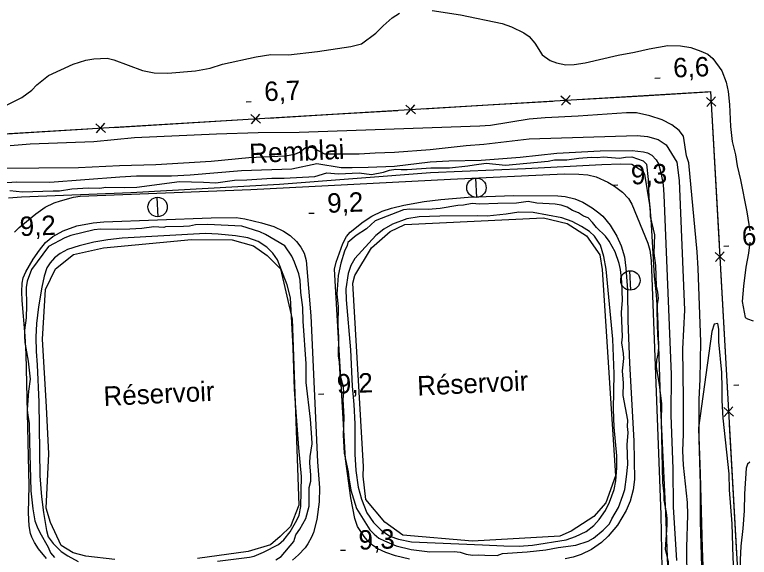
# Model space of a CAD drawing. Extents: x 336540 to 340074, y 5572036 to 5573747.
# Drawn here: x 337475.9 to 337589.4, y 5572956.1 to 5573040 of the extents above; entities that cross this region are included whole.
import ezdxf

# ---------------------------------------------------------------- set-up
doc = ezdxf.new("R2010")
doc.units = 0
for name, color, linetype in [('Niveau 19', 7, 'Continuous'), ('Niveau 2', 7, 'Continuous'), ('Niveau 27', 7, 'Continuous'), ('Niveau 3', 7, 'Continuous'), ('Niveau 33', 7, 'Continuous'), ('Niveau 36', 7, 'Continuous'), ('Niveau 37', 7, 'Continuous')]:
    doc.layers.add(name, color=color, linetype=linetype)

msp = doc.modelspace()

# ---------------------------------------------------------------- linework, layer by layer
at = {"layer": 'Niveau 19'}
for points in [[(337475.82, 5573006.41), (337476.57, 5573007.11), (337479.15, 5573009.22), (337480.58, 5573010.26), (337481.94, 5573010.91), (337482.94, 5573011.25), (337484.96, 5573011.78), (337485.99, 5573011.93), (337512.36, 5573012.99), (337543.2, 5573014.59), (337560.77, 5573015.4), (337563.06, 5573015.37), (337564.43, 5573015.27), (337565.73, 5573014.95), (337567.53, 5573014.12), (337568.56, 5573013.5), (337569.78, 5573012.56), (337570.74, 5573011.57), (337571.26, 5573010.73), (337573.73, 5573004.71)], [(337527.01, 5572971.35), (337525.26, 5573000.67), (337525.55, 5573001.75), (337526.59, 5573004.66), (337527.16, 5573005.7), (337527.72, 5573006.37), (337529.7, 5573007.97), (337531.03, 5573008.85), (337532.64, 5573009.61), (337534.08, 5573010.1), (337536, 5573010.58), (337539.13, 5573011.14), (337541.7, 5573011.45), (337545.93, 5573011.81), (337552.97, 5573012.08), (337559.78, 5573012), (337560.94, 5573011.89), (337562.41, 5573011.54), (337563.64, 5573011.04), (337565.1, 5573010.17), (337566.13, 5573009.4), (337566.73, 5573008.84), (337567.88, 5573007.49), (337568.92, 5573005.78), (337569.57, 5573004.28), (337570.08, 5573002.59), (337570.33, 5573000.8), (337570.55, 5572997.49), (337570.64, 5572992.69), (337570.9, 5572986.15), (337571.53, 5572974.14), (337571.63, 5572968.17), (337571.42, 5572966.56), (337570.98, 5572964.79), (337570.38, 5572963.36), (337569.01, 5572961.07), (337567.58, 5572959.37), (337566.55, 5572958.41), (337564.99, 5572957.33), (337563.39, 5572956.57), (337562.16, 5572956.15), (337560.94, 5572955.9)], [(337480.8, 5572955.95), (337479.56, 5572957.44), (337478.93, 5572958.43), (337478.52, 5572959.25), (337478.33, 5572959.79), (337478.11, 5572961.01), (337478.02, 5572962.97), (337478.12, 5572967.18), (337477.63, 5572987.52), (337477.48, 5572990.38), (337477.02, 5572995.83), (337476.96, 5572997.17), (337477.01, 5572998.51), (337477.19, 5572999.32), (337477.58, 5573000.24), (337478.74, 5573002.23), (337479.68, 5573003.61), (337480.62, 5573004.77), (337481.74, 5573005.74), (337483.37, 5573006.59), (337485.49, 5573007.36), (337487.99, 5573007.82), (337489.63, 5573007.96), (337506.2, 5573008.62), (337510.08, 5573008.68), (337511.44, 5573008.47), (337514.02, 5573007.84), (337515.89, 5573007.26), (337517.42, 5573006.56), (337518.42, 5573005.85), (337519.42, 5573004.94), (337520.1, 5573004.09), (337520.6, 5573003.14), (337520.92, 5573002), (337521.61, 5572993.43), (337522.64, 5572970.87)], [(337573.73, 5573004.71), (337574.03, 5573003.62), (337574.24, 5573002.02), (337575.74, 5572962.68), (337575.87, 5572954.34), (337575.78, 5572953.58), (337575.21, 5572952.2), (337574.63, 5572951.26), (337573.73, 5572950.18), (337572.28, 5572948.79), (337571.01, 5572948), (337569.12, 5572947.08), (337566.32, 5572945.88), (337562.31, 5572944.34), (337561.12, 5572943.72), (337558.63, 5572941.81), (337557.03, 5572939.27)], [(337522.64, 5572970.87), (337522.96, 5572966.87), (337522.9, 5572964.72), (337522.57, 5572961.94), (337522.05, 5572959.97), (337521.75, 5572959.22), (337521.18, 5572958.18), (337520.73, 5572957.57), (337519.74, 5572956.49), (337518.77, 5572955.68)], [(337536.89, 5572955.82), (337534.72, 5572956.34), (337533.22, 5572956.86), (337531.97, 5572957.44), (337531.16, 5572957.99), (337530.31, 5572958.79), (337529.85, 5572959.34), (337528.85, 5572960.89), (337528.42, 5572962.13), (337527.81, 5572965.32), (337527.01, 5572971.35)]]:
    msp.add_lwpolyline(points, dxfattribs=at)
at = {"layer": 'Niveau 2'}
for points in [[(337473.22, 5573025.35), (337476.95, 5573027.23), (337478.5, 5573028.32), (337479.28, 5573029.16), (337481.11, 5573030.62), (337484.88, 5573032.35), (337486.88, 5573032.99), (337488.09, 5573033.16), (337490.13, 5573033.28), (337491.16, 5573033.04), (337495.61, 5573031.39), (337497.4, 5573031.02), (337499.52, 5573030.96), (337503.8, 5573031.34), (337506.08, 5573031.75), (337507.97, 5573032.35), (337513.16, 5573033.51), (337515.46, 5573033.83), (337518.18, 5573033.79), (337522.68, 5573034.31), (337527.8, 5573035.07), (337529.45, 5573035.49), (337531.69, 5573037.14), (337532.79, 5573038.31), (337534.18, 5573039.52), (337535.35, 5573040.27)], [(337540.36, 5573040.66), (337544.75, 5573039.98), (337551.18, 5573038.66), (337552.65, 5573038.12), (337554.56, 5573037.18), (337555.37, 5573036.62)], [(337555.37, 5573036.62), (337556.26, 5573035.63), (337557.37, 5573033.78), (337558.6, 5573032.93), (337559.58, 5573032.55), (337561.04, 5573032.24), (337562.33, 5573032.31), (337564.04, 5573032.58), (337569.1, 5573033.77), (337571.65, 5573034.22), (337573.9, 5573034.75), (337576.8, 5573035.24), (337578.77, 5573035.22), (337580.36, 5573034.93), (337581.92, 5573034.38), (337582.96, 5573033.91), (337583.76, 5573033.24), (337585.14, 5573031.31), (337585.82, 5573029.56), (337586.12, 5573028.14), (337586.33, 5573026.11), (337586.5, 5573022.72), (337586.75, 5573020.38), (337587.24, 5573018.34), (337587.5, 5573016.62), (337588.04, 5573014.49), (337589, 5573009.53), (337589.45, 5573006.59)], [(337506.25, 5573017.34), (337512.06, 5573017.91), (337517.64, 5573018.17), (337519.15, 5573018.47), (337519.86, 5573018.78), (337520.95, 5573019.6), (337521.86, 5573019.49), (337523.74, 5573018.52), (337529.09, 5573018.5), (337531.59, 5573018.67), (337534.54, 5573018.76), (337540.05, 5573019.17), (337545.65, 5573019.79), (337548.36, 5573019.99), (337555.37, 5573020.82), (337572.06, 5573021.34), (337573.64, 5573021.2), (337575.29, 5573020.72), (337576.53, 5573019.91), (337578.17, 5573017.23), (337578.54, 5573014.38), (337579.38, 5572994.32)], [(337473.82, 5573014.01), (337476.19, 5573014.17), (337481.3, 5573014.1), (337492.12, 5573014.95), (337494.67, 5573015.08), (337500.1, 5573015.11), (337502.99, 5573015.23), (337510.91, 5573015.9), (337518.67, 5573016.16), (337522.54, 5573017.02), (337526.33, 5573016.4), (337528.01, 5573016.36), (337530.49, 5573016.43), (337534.55, 5573016.6), (337540.07, 5573017.25), (337542.96, 5573017.44), (337547.97, 5573017.53), (337553.96, 5573017.97), (337559.67, 5573018.58), (337566.34, 5573018.98), (337571.27, 5573019.01), (337573.05, 5573018.81), (337573.64, 5573018.63), (337574.34, 5573018.27), (337575.01, 5573017.57), (337575.35, 5573016.96), (337575.71, 5573015.61), (337576.07, 5573013.69), (337576.19, 5573012.15), (337577.31, 5572984.38), (337577.24, 5572978.08), (337577.55, 5572969.79), (337577.61, 5572963.9), (337578.15, 5572955.62)], [(337473.43, 5573016.26), (337485.74, 5573016.39), (337492.07, 5573016.7), (337497.66, 5573016.87), (337506.25, 5573017.34)], [(337475.13, 5573012.81), (337477.05, 5573012.63), (337481.82, 5573012.8), (337482.78, 5573012.76), (337484.68, 5573013.09), (337487.26, 5573013.26), (337489.01, 5573013.19), (337489.96, 5573013.33), (337492.83, 5573013.28), (337494.74, 5573013.33), (337501.35, 5573014.22), (337505.06, 5573014.14), (337506.97, 5573014.01), (337509.83, 5573014.42), (337511.74, 5573014.47), (337515.61, 5573014.73), (337517.52, 5573014.72), (337522.23, 5573015), (337524.08, 5573015.55), (337525.88, 5573015.42), (337529.08, 5573015.55), (337530.99, 5573015.32), (337532.84, 5573015.64), (337533.79, 5573015.95), (337534.74, 5573016.14), (337535.58, 5573016.05), (337536.54, 5573016.07), (337540.19, 5573016.32), (337543.05, 5573016.34), (337545.91, 5573016.63), (337546.86, 5573016.82), (337548.71, 5573017.03), (337551.69, 5573016.77), (337558.31, 5573017.38), (337559.26, 5573017.57), (337561.17, 5573017.56), (337563.02, 5573017.83), (337564.93, 5573017.98), (337565.88, 5573017.95), (337566.84, 5573018.03), (337569.32, 5573017.81), (337570.27, 5573018), (337571.22, 5573018.02), (337572.98, 5573017.39), (337573.5, 5573016.89), (337573.78, 5573014.54), (337573.84, 5573011.67), (337574.06, 5573009.77), (337574.08, 5573008.81), (337574.76, 5573005.96), (337574.66, 5573003.15), (337574.87, 5573001.24), (337575.01, 5572998.04), (337575.2, 5572997.09), (337575.28, 5572996.14), (337575.13, 5572995.18), (337575.1, 5572994.22), (337575.19, 5572990.4), (337575.32, 5572989.45), (337575.34, 5572988.5), (337575.25, 5572987.54), (337575.05, 5572986.58), (337575.02, 5572985.62), (337575.48, 5572982.77), (337575.83, 5572979.91), (337575.78, 5572977.04), (337575.95, 5572967.66), (337576.16, 5572965.92), (337576.18, 5572964.96)], [(337568.16, 5572962.07), (337569.18, 5572963.84), (337569.87, 5572965.66), (337570.13, 5572966.62), (337570.42, 5572968.54), (337570.6, 5572970.45), (337570.53, 5572973.49), (337570.65, 5572975.4), (337570.57, 5572976.35), (337570.61, 5572977.31), (337569.9, 5572981.11), (337569.97, 5572983.03), (337569.81, 5572984.93), (337569.99, 5572986.85), (337569.97, 5572987.64), (337569.71, 5572989.26), (337569.8, 5572990.22), (337569.65, 5572993.98), (337569.78, 5572995.89), (337569.71, 5572998.7), (337569.5, 5573000.61), (337569.3, 5573001.56), (337568.64, 5573003.34), (337567.71, 5573005.01), (337567.18, 5573005.78), (337565.75, 5573007.1), (337565.17, 5573007.87), (337564.48, 5573008.58), (337563.79, 5573008.85), (337563, 5573009.39), (337562.09, 5573009.76), (337561.23, 5573010.25), (337560.33, 5573010.57), (337559.37, 5573010.71), (337556.55, 5573010.87), (337555.2, 5573011.12), (337553.41, 5573010.85), (337550.54, 5573010.84), (337547.68, 5573010.71), (337546.55, 5573010.8), (337545.21, 5573010.54), (337544.37, 5573010.52), (337541.63, 5573010.06), (337539.77, 5573009.91), (337536.91, 5573009.95), (337535.96, 5573009.82), (337531.56, 5573008.14), (337530.24, 5573006.92), (337528.63, 5573005.87), (337527.36, 5573004.78), (337527.26, 5573004.32), (337526.83, 5573003.47), (337526.26, 5573001.6), (337525.86, 5572999.68), (337525.64, 5572996.81), (337525.86, 5572994.9), (337525.81, 5572992.03), (337525.91, 5572990.13), (337525.87, 5572987.26), (337526, 5572986.31), (337526.1, 5572984.4), (337526.65, 5572982.5), (337526.68, 5572981.54), (337526.59, 5572980.59), (337526.71, 5572977.72), (337526.61, 5572975.08), (337526.79, 5572972.22), (337527.41, 5572969.36), (337527.49, 5572968.41), (337527.82, 5572966.51), (337528.67, 5572963.66), (337530.72, 5572960.39), (337531.41, 5572959.68), (337532.15, 5572959.08), (337533.01, 5572958.65), (337534.82, 5572957.91), (337537.14, 5572957.34), (337540.01, 5572956.96), (337543.78, 5572957), (337544.73, 5572956.91), (337545.64, 5572956.59), (337546.6, 5572956.45), (337547.55, 5572956.52), (337548.51, 5572956.43), (337550.42, 5572956.42), (337551.26, 5572956.72), (337555.07, 5572956.98), (337557.93, 5572957.28), (337559.83, 5572957.66), (337562.58, 5572958.01), (337564.47, 5572958.61), (337565.3, 5572959.08), (337566.79, 5572960.3), (337567.78, 5572961.28), (337568.16, 5572962.07)], [(337548.16, 5572958.06), (337551.46, 5572957.88), (337553.82, 5572957.86), (337555.89, 5572958), (337561.08, 5572958.81), (337562.53, 5572959.35), (337564.17, 5572960.12), (337565.34, 5572961.03), (337566.19, 5572961.99), (337567.17, 5572963.36), (337567.77, 5572964.63), (337568.49, 5572966.58), (337568.75, 5572967.94), (337568.93, 5572969.96), (337568.92, 5572971.83), (337568.5, 5572976.25), (337568.42, 5572979.04), (337568.5, 5572984.47), (337568.29, 5572989.87), (337567.25, 5573000.66), (337566.92, 5573002.6), (337566.38, 5573004.39), (337565.46, 5573005.78), (337564.69, 5573006.47), (337563.44, 5573007.28), (337561.99, 5573008.02), (337560.44, 5573008.6), (337555.99, 5573009.43), (337553.77, 5573009.48), (337551.83, 5573009.17), (337548.89, 5573008.85), (337547.33, 5573008.91), (337541.58, 5573008.87), (337538.37, 5573008.76), (337536.48, 5573008.45), (337534.24, 5573007.62), (337532.91, 5573006.84), (337531.68, 5573005.85), (337528.41, 5573002.32), (337527.8, 5573001.23), (337527.39, 5573000.01), (337527.06, 5572997.64), (337527.1, 5572995.9), (337527.75, 5572988.18), (337528.03, 5572982.57), (337528.29, 5572979.75), (337528.41, 5572976.78), (337528.42, 5572972.06), (337528.6, 5572969.55), (337528.96, 5572966.97), (337529.44, 5572965.12), (337530.29, 5572963.02), (337531.3, 5572961.49), (337532.48, 5572960.3), (337533.85, 5572959.37), (337535.19, 5572958.93), (337537.16, 5572958.53), (337548.16, 5572958.06)], [(337519.33, 5572959.62), (337519.93, 5572960.47), (337520.84, 5572962.12), (337521.36, 5572964.05), (337521.35, 5572966.91), (337521.61, 5572967.88), (337521.64, 5572968.83), (337521.48, 5572970.74), (337521.52, 5572971.7), (337521.81, 5572973.67), (337521.78, 5572974.63), (337521.6, 5572977.49), (337520.91, 5572983.15), (337520.9, 5572986.01), (337520.46, 5572992.64), (337520.41, 5572994.72), (337520.07, 5572997.07), (337519.97, 5572998.98), (337519.78, 5572999.93), (337519.12, 5573001.77), (337518.7, 5573002.66), (337517.6, 5573004.26), (337514.63, 5573006.05), (337513.73, 5573006.42), (337510.95, 5573007.31), (337505.66, 5573007.57), (337503.81, 5573007.53), (337502.86, 5573007.34), (337501.96, 5573007.26), (337499.15, 5573007.19), (337498.93, 5573007.13), (337497.35, 5573007.21), (337495.51, 5573006.94), (337493.65, 5573006.84), (337491.74, 5573006.79), (337489.1, 5573006.84), (337488.15, 5573006.76), (337484.52, 5573005.89), (337483.62, 5573005.53), (337481.07, 5573004.18), (337478.46, 5573000.63), (337477.77, 5572998.81), (337477.62, 5572997.85), (337477.69, 5572995.05), (337477.62, 5572993.13), (337477.39, 5572991.22), (337477.36, 5572990.26), (337477.43, 5572989.31), (337477.95, 5572986.45), (337478.24, 5572983.65), (337478.01, 5572981.79), (337477.79, 5572978.91), (337477.87, 5572978.02), (337478.12, 5572976.84), (337478.13, 5572973.98), (337478.37, 5572966.39), (337478.66, 5572963.59), (337478.99, 5572961.74), (337479.35, 5572960.85), (337479.76, 5572959.96), (337481.05, 5572957.69), (337481.41, 5572956.8), (337481.99, 5572956.08)], [(337507.22, 5572955.53), (337512.14, 5572956.16), (337512.88, 5572956.31), (337514.31, 5572956.89), (337516.64, 5572958.08), (337517.48, 5572958.8), (337518.43, 5572960.06), (337519.48, 5572961.85), (337519.84, 5572962.64), (337520.07, 5572964), (337520.21, 5572968.63), (337519.79, 5572973.03), (337519.11, 5572982.08), (337518.9, 5572988.49), (337518.47, 5572996.25), (337517.95, 5572998.23), (337516.47, 5573002.11), (337515.75, 5573003.14), (337514.83, 5573004.07), (337513.5, 5573004.96), (337511.91, 5573005.49), (337509.96, 5573005.81), (337507.29, 5573006.08), (337505.37, 5573006.16), (337492.48, 5573005.45), (337490.28, 5573005.2), (337488.08, 5573004.82), (337485.82, 5573004.28), (337484.02, 5573003.69), (337482.87, 5573003.1), (337482, 5573002.43), (337481.32, 5573001.67), (337480.84, 5573000.85), (337480.43, 5572999.56), (337480.08, 5572997.88), (337479.55, 5572994.83), (337479.24, 5572992.29), (337479.14, 5572990.16), (337479.17, 5572987.95), (337479.36, 5572985.86), (337479.6, 5572980.11), (337479.74, 5572968.72), (337479.99, 5572965.49), (337480.3, 5572963.04), (337480.77, 5572960.26), (337481.06, 5572959.28), (337481.82, 5572958.24), (337483.06, 5572957.01), (337484.06, 5572956.34), (337485.67, 5572955.48)], [(337589.47, 5573004.85), (337589.28, 5573003.15), (337588.87, 5573000.99), (337588.47, 5572998.02), (337588.31, 5572995.69), (337588.73, 5572993.19), (337589.1, 5572992.97), (337589.99, 5572992.69)], [(337579.38, 5572994.32), (337579.07, 5572988.36), (337579.18, 5572980.61), (337579.17, 5572975.17), (337579.08, 5572972.6), (337579.17, 5572970.36), (337579.79, 5572964.57), (337579.84, 5572962.67), (337579.69, 5572957.63), (337579.74, 5572952.43)], [(337586.29, 5572969.05), (337585.36, 5572977.64), (337585.19, 5572980.37), (337585.22, 5572982.25), (337585.13, 5572984.67), (337584.69, 5572989.42), (337584.67, 5572991.39), (337584.54, 5572992.29), (337583.94, 5572992.17), (337583.58, 5572991.01), (337581.52, 5572976.14), (337581.81, 5572967.37), (337581.79, 5572961.65), (337582.15, 5572949.44)], [(337589.48, 5572970.82), (337589.11, 5572970.51), (337588.92, 5572969.88), (337588.67, 5572965.93), (337588.59, 5572963.28), (337588.38, 5572960.59), (337588.06, 5572957.82), (337587.97, 5572955.72), (337588.15, 5572950.67), (337588.04, 5572948.54), (337588.08, 5572946.27), (337588.45, 5572940.88), (337588.44, 5572938.94), (337588.29, 5572936.69), (337587.9, 5572936.72), (337587.57, 5572937.33), (337587.33, 5572941.04), (337587.4, 5572943.09), (337587.07, 5572953.07), (337586.87, 5572956.1), (337586.76, 5572961.31), (337586.34, 5572966.57), (337586.29, 5572969.05)], [(337576.18, 5572964.96), (337576.56, 5572963.06), (337576.64, 5572962.11), (337576.66, 5572961.15), (337576.41, 5572957.33), (337576.85, 5572955.48), (337576.87, 5572954.53), (337576.58, 5572952.61), (337576.68, 5572950.93), (337576.21, 5572949.34), (337575.52, 5572947.53), (337574.95, 5572945.66), (337574.49, 5572943.79), (337574.1, 5572943.45), (337573.27, 5572942.92), (337571.2, 5572942.65), (337568.35, 5572941.79), (337567.4, 5572941.77), (337566.45, 5572941.52), (337564.82, 5572941.48), (337560.11, 5572941.14), (337558.23, 5572941.21)], [(337516.22, 5572955.72), (337517.05, 5572956.24), (337519.02, 5572958.54), (337519.33, 5572959.62)]]:
    msp.add_lwpolyline(points, dxfattribs=at)
at = {"layer": 'Niveau 27'}
for points in [[(337582.59, 5572946.44), (337582.16, 5572957.53), (337581.86, 5572968.97), (337581.62, 5572974.82), (337581.65, 5572980.54), (337581.79, 5572983.64), (337581.9, 5572989.45), (337581.49, 5573000.77), (337581.34, 5573003.34), (337580.02, 5573017.09), (337579.7, 5573018.18), (337579.22, 5573021.21), (337578.55, 5573022.11), (337577.42, 5573022.98), (337575.91, 5573023.75), (337574.03, 5573024.38), (337571.94, 5573024.85), (337570.39, 5573024.85), (337562.94, 5573024.3), (337557.86, 5573024.07), (337555.37, 5573023.84), (337549.41, 5573022.86), (337547.72, 5573022.77), (337519.84, 5573021.79), (337513.5, 5573021.72), (337507.05, 5573021.54), (337494.39, 5573020.95), (337488.09, 5573020.37), (337478.23, 5573019.98), (337475.17, 5573019.74)], [(337474.92, 5573011.72), (337476.89, 5573011.86), (337493.79, 5573012.52), (337516.76, 5573013.82), (337540.13, 5573015.63), (337554.78, 5573016.22), (337566.62, 5573016.84), (337569.53, 5573016.95), (337571.21, 5573016.9), (337572.92, 5573015.82), (337573.17, 5573015.33), (337573.98, 5573010.59), (337574.18, 5573008.4), (337574.68, 5572999.56), (337574.99, 5572996.72), (337575.21, 5572993.54), (337575.64, 5572979.19), (337576.43, 5572963.02), (337577.18, 5572943.76)]]:
    msp.add_lwpolyline(points, dxfattribs=at)
at = {"layer": 'Niveau 3'}
for p, q in [((337574.81, 5573030.21), (337575.61, 5573030.25)), ((337511.61, 5573026.56), (337512.4, 5573026.59)), ((337568.29, 5573013.67), (337569.09, 5573013.71)), ((337521.34, 5573009.3), (337522.14, 5573009.32)), ((337585.43, 5573004.21), (337586.23, 5573004.25)), ((337586.98, 5572982.74), (337587.78, 5572982.78)), ((337522.83, 5572981.34), (337523.63, 5572981.38)), ((337526.19, 5572957.2), (337526.99, 5572957.24))]:
    msp.add_line(p, q, dxfattribs=at)
at = {"layer": 'Niveau 33'}
for points in [[(337529.79, 5572970.15), (337528.14, 5572998.48), (337528.44, 5572999.7), (337531.01, 5573003.94), (337533.9, 5573006.5), (337536.14, 5573007.58), (337557.58, 5573008.62), (337561.25, 5573007.71), (337564.24, 5573005.8), (337566.31, 5573002.87), (337566.66, 5573000.59), (337568.69, 5572968.74), (337567.2, 5572964.55), (337565.38, 5572962.41), (337561.86, 5572960.18), (337560.09, 5572959.37), (337546.61, 5572958.59), (337535.82, 5572959.52), (337533.07, 5572961.56), (337530.12, 5572965.05), (337529.7, 5572968.66), (337529.79, 5572970.15)], [(337480.74, 5572963.72), (337481.13, 5572972.11), (337480.78, 5572979.36), (337480.15, 5572989.86), (337480.62, 5572997.5), (337482.16, 5573000.72), (337484.95, 5573002.92), (337489.6, 5573003.99), (337503.18, 5573005.25), (337509.46, 5573005.19), (337512.77, 5573004.27), (337514.89, 5573002.8), (337516.92, 5573000.72), (337518.75, 5572992.94), (337519.78, 5572964.19), (337518.49, 5572960.86), (337516.88, 5572959.33), (337515.37, 5572958.04), (337511.92, 5572957.03), (337504.13, 5572955.92)], [(337491.34, 5572955.79), (337486.85, 5572956.3), (337484.89, 5572956.81), (337483.03, 5572957.93), (337481.41, 5572961.48), (337480.74, 5572963.72)]]:
    msp.add_lwpolyline(points, dxfattribs=at)
at = {"layer": 'Niveau 36'}
for p, q in [((337547.3, 5573011.75), (337547.15, 5573014.74)), ((337498.03, 5573008.77), (337497.88, 5573011.76)), ((337571.09, 5572997.42), (337570.94, 5573000.41))]:
    msp.add_line(p, q, dxfattribs=at)
for centre in [(337547.22, 5573013.26), (337497.95, 5573010.28), (337571.01, 5572998.93)]:
    msp.add_circle(centre, 1.5, dxfattribs=at)
at = {"layer": 'Niveau 37'}
for p, q in [((337561.76, 5573026.11), (337560.27, 5573027.43)), ((337560.35, 5573026.02), (337561.68, 5573027.52)), ((337582.83, 5573025.8), (337584.16, 5573027.29)), ((337582.75, 5573027.21), (337584.24, 5573025.88)), ((337537.81, 5573024.67), (337536.31, 5573026)), ((337536.39, 5573024.59), (337537.72, 5573026.09)), ((337513.85, 5573023.24), (337512.35, 5573024.57)), ((337512.44, 5573023.15), (337513.77, 5573024.65)), ((337489.89, 5573021.8), (337488.4, 5573023.13)), ((337488.48, 5573021.72), (337489.81, 5573023.22)), ((337584.09, 5573003.25), (337585.59, 5573001.92)), ((337584.17, 5573001.84), (337585.51, 5573003.33)), ((337585.44, 5572979.29), (337586.93, 5572977.95)), ((337585.52, 5572977.88), (337586.85, 5572979.37))]:
    msp.add_line(p, q, dxfattribs=at)
for points in [[(337543.85, 5572928.37), (337465.55, 5572924.24), (337460.25, 5573020.74), (337583.41, 5573028.11), (337588.84, 5572931.19), (337559.32, 5572929.42), (337558.81, 5572938.85), (337543.51, 5572937.69), (337543.85, 5572928.37)], [(337563.01, 5573026.89), (337572.99, 5573027.49)], [(337572.99, 5573027.49), (337582.98, 5573028.08)], [(337549.04, 5573026.05), (337559.02, 5573026.65)], [(337525.08, 5573024.62), (337535.06, 5573025.22)], [(337539.05, 5573025.46), (337549.04, 5573026.05)], [(337515.1, 5573024.02), (337525.08, 5573024.62)], [(337583.61, 5573024.55), (337584.17, 5573014.57)], [(337491.14, 5573022.59), (337501.12, 5573023.19)], [(337501.12, 5573023.19), (337511.1, 5573023.78)], [(337467.18, 5573021.15), (337477.17, 5573021.75)], [(337477.17, 5573021.75), (337487.15, 5573022.35)], [(337584.17, 5573014.57), (337584.73, 5573004.58)], [(337584.95, 5573000.59), (337585.51, 5572990.6)], [(337585.51, 5572990.6), (337586.07, 5572980.62)], [(337586.29, 5572976.63), (337586.85, 5572966.64)], [(337586.85, 5572966.64), (337587.41, 5572956.66)]]:
    msp.add_lwpolyline(points, dxfattribs=at)

# ---------------------------------------------------------------- texts
at = {"layer": 'Niveau 27'}
msp.add_text('Remblai', height=3, rotation=2.7781, dxfattribs=at).set_placement((337512.18, 5573017.03))
at = {"layer": 'Niveau 3'}
for s, p in [('6,6    ', (337577.68, 5573030.29)), ('6,7    ', (337514.48, 5573026.63)), ('9,3    ', (337571.16, 5573013.75)), ('9,2    ', (337524.22, 5573009.37)), ('9,2    ', (337476.7, 5573005.77)), ('6,7    ', (337588.3, 5573004.29)), ('9,2    ', (337525.7, 5572981.42)), ('9,3    ', (337529.06, 5572957.28))]:
    msp.add_text(s, height=3, rotation=2.2763, dxfattribs=at).set_placement(p)
at = {"layer": 'Niveau 33'}
for p in [(337538.14, 5572981.11), (337489.66, 5572979.51)]:
    msp.add_text('Réservoir', height=3, rotation=2.7781, dxfattribs=at).set_placement(p)

doc.saveas('drawing.dxf')
